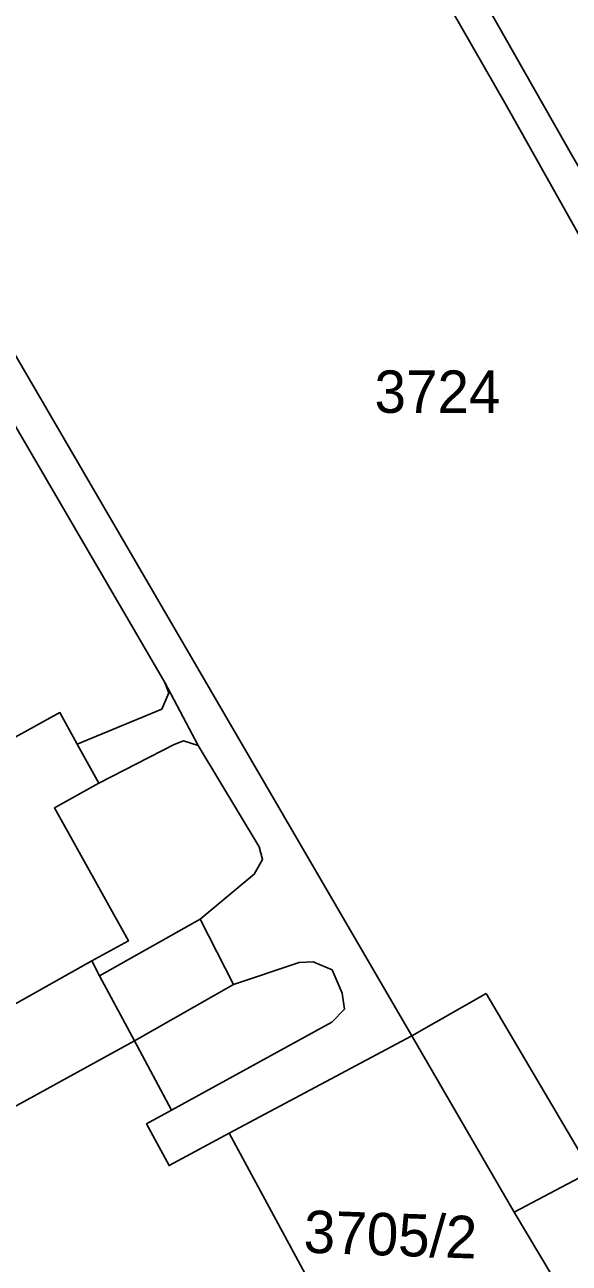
# Model space of a CAD drawing. Extents: x -262715 to -259381, y -1237238 to -1231182.
# Drawn here: x -261764.4 to -261738.7, y -1235545.6 to -1235487.1 of the extents above; entities that cross this region are included whole.
import ezdxf

# ---------------------------------------------------------------- set-up
doc = ezdxf.new("R2010")
doc.units = 0
for name, color, linetype in [('body_kn', 7, 'Continuous'), ('kladpar_druhypozemkov', 7, 'Continuous'), ('kladpar_hranice', 7, 'Continuous'), ('kladpar_parcelnecisla', 7, 'Continuous'), ('kladpar_plochy', 7, 'Continuous'), ('zappar_hrandruhpozemk', 7, 'Continuous')]:
    doc.layers.add(name, color=color, linetype=linetype)

msp = doc.modelspace()

# ---------------------------------------------------------------- linework, layer by layer
at = {"layer": 'body_kn'}
for p, q in [((-261741.69, -1235490.92), (-261741.69, -1235490.92)), ((-261757.81, -1235518.16), (-261757.81, -1235518.16)), ((-261757.81, -1235518.16), (-261757.81, -1235518.16)), ((-261757.61, -1235518.64), (-261757.61, -1235518.64)), ((-261762.76, -1235519.57), (-261762.76, -1235519.57)), ((-261757.94, -1235519.41), (-261757.94, -1235519.41)), ((-261756.92, -1235520.9), (-261756.92, -1235520.9)), ((-261761.94, -1235521.06), (-261761.94, -1235521.06)), ((-261757.36, -1235521.08), (-261757.36, -1235521.08)), ((-261756.23, -1235521.12), (-261756.23, -1235521.12)), ((-261760.92, -1235522.9), (-261760.92, -1235522.9)), ((-261760.92, -1235522.9), (-261760.92, -1235522.9)), ((-261763.02, -1235524.07), (-261763.02, -1235524.07)), ((-261753.35, -1235525.9), (-261753.35, -1235525.9)), ((-261753.19, -1235526.5), (-261753.19, -1235526.5)), ((-261753.58, -1235527.19), (-261753.58, -1235527.19)), ((-261756.13, -1235529.32), (-261756.13, -1235529.32)), ((-261759.52, -1235530.35), (-261759.52, -1235530.35)), ((-261761.25, -1235531.29), (-261761.25, -1235531.29)), ((-261761.25, -1235531.29), (-261761.25, -1235531.29)), ((-261751.46, -1235531.37), (-261751.46, -1235531.37)), ((-261750.8, -1235531.33), (-261750.8, -1235531.33)), ((-261760.88, -1235531.99), (-261760.88, -1235531.99)), ((-261749.9, -1235531.71), (-261749.9, -1235531.71)), ((-261754.56, -1235532.41), (-261754.56, -1235532.41)), ((-261754.56, -1235532.41), (-261754.56, -1235532.41)), ((-261749.43, -1235532.81), (-261749.43, -1235532.81)), ((-261742.63, -1235532.83), (-261742.63, -1235532.83)), ((-261749.32, -1235533.57), (-261749.32, -1235533.57)), ((-261749.92, -1235534.18), (-261749.92, -1235534.18)), ((-261746.14, -1235534.82), (-261746.14, -1235534.82)), ((-261746.14, -1235534.82), (-261746.14, -1235534.82)), ((-261759.24, -1235535.06), (-261759.24, -1235535.06)), ((-261759.24, -1235535.06), (-261759.24, -1235535.06)), ((-261757.48, -1235538.34), (-261757.48, -1235538.34)), ((-261757.48, -1235538.34), (-261757.48, -1235538.34)), ((-261758.67, -1235538.98), (-261758.67, -1235538.98)), ((-261754.77, -1235539.41), (-261754.77, -1235539.41)), ((-261757.6, -1235540.95), (-261757.6, -1235540.95)), ((-261741.3, -1235543.14), (-261741.3, -1235543.14))]:
    msp.add_line(p, q, dxfattribs=at)
at = {"layer": 'kladpar_druhypozemkov'}
for p, q in [((-261745.23, -1235503.27), (-261745.23, -1235503.27)), ((-261746.47, -1235543.12), (-261746.47, -1235543.12))]:
    msp.add_line(p, q, dxfattribs=at)
at = {"layer": 'kladpar_hranice'}
for points in [[(-261703.82, -1235554.81), (-261717.49, -1235533.49), (-261720.95, -1235535.54), (-261724.65, -1235529.36), (-261721.21, -1235527.35), (-261741.69, -1235490.92), (-261746.46, -1235482.59), (-261762.17, -1235454.92), (-261767.41, -1235457.85), (-261769.12, -1235454.68), (-261763.9, -1235451.67), (-261773.09, -1235436.12), (-261752.11, -1235424.22), (-261749.95, -1235426.33)], [(-261702.44, -1235554.03), (-261718.94, -1235528.05), (-261721.43, -1235523.65), (-261727.61, -1235512.61), (-261729.76, -1235508.8), (-261736.11, -1235497.5), (-261738.53, -1235493.35), (-261744.87, -1235482.21), (-261747.16, -1235478.14), (-261753.42, -1235467.18), (-261755.87, -1235462.99), (-261762.27, -1235451.12), (-261763.94, -1235448.17), (-261769.25, -1235438.72), (-261769.14, -1235437.7), (-261768.42, -1235436.65), (-261749.95, -1235426.33)], [(-261749.95, -1235426.33), (-261768.42, -1235436.65), (-261769.14, -1235437.7), (-261769.25, -1235438.72), (-261763.94, -1235448.17), (-261762.27, -1235451.12), (-261755.87, -1235462.99), (-261753.42, -1235467.18), (-261747.16, -1235478.14), (-261744.87, -1235482.21), (-261738.53, -1235493.35), (-261736.11, -1235497.5), (-261729.76, -1235508.8), (-261727.61, -1235512.61), (-261721.43, -1235523.65), (-261718.94, -1235528.05), (-261702.44, -1235554.03)], [(-261738.88, -1235547.2), (-261741.3, -1235543.14), (-261746.14, -1235534.82), (-261766.01, -1235500.78), (-261784.25, -1235467.69), (-261779.97, -1235465.46), (-261783.5, -1235458.95), (-261787.77, -1235460.98), (-261787.21, -1235451.46), (-261786.03, -1235450.8), (-261783.26, -1235442.31), (-261774.22, -1235436.76), (-261773.09, -1235436.12)], [(-261773.09, -1235436.12), (-261763.9, -1235451.67), (-261769.12, -1235454.68), (-261767.41, -1235457.85), (-261762.17, -1235454.92), (-261746.46, -1235482.59), (-261741.69, -1235490.92), (-261721.21, -1235527.35), (-261724.65, -1235529.36), (-261720.95, -1235535.54), (-261717.49, -1235533.49), (-261703.82, -1235554.81)], [(-261784.25, -1235467.69), (-261766.01, -1235500.78), (-261746.14, -1235534.82), (-261754.77, -1235539.41), (-261757.6, -1235540.95), (-261758.67, -1235538.98), (-261757.48, -1235538.34), (-261759.24, -1235535.06), (-261760.88, -1235531.99), (-261756.13, -1235529.32), (-261753.58, -1235527.19), (-261753.19, -1235526.5), (-261753.35, -1235525.9), (-261756.23, -1235521.12), (-261757.81, -1235518.16), (-261764.84, -1235506.09), (-261766.79, -1235502.5), (-261773.05, -1235491.54), (-261775.39, -1235487.37), (-261780.72, -1235477.75)], [(-261764.84, -1235506.09), (-261757.81, -1235518.16), (-261756.23, -1235521.12), (-261753.35, -1235525.9), (-261753.19, -1235526.5), (-261753.58, -1235527.19), (-261756.13, -1235529.32), (-261760.88, -1235531.99), (-261761.25, -1235531.29), (-261759.52, -1235530.35), (-261763.02, -1235524.07), (-261760.92, -1235522.9), (-261761.94, -1235521.06), (-261762.76, -1235519.57), (-261764.87, -1235520.74)], [(-261764.87, -1235520.74), (-261762.76, -1235519.57), (-261761.94, -1235521.06), (-261760.92, -1235522.9), (-261763.02, -1235524.07), (-261759.52, -1235530.35), (-261761.25, -1235531.29), (-261770.7, -1235536.59)], [(-261761.25, -1235531.29), (-261760.88, -1235531.99), (-261759.24, -1235535.06), (-261757.48, -1235538.34), (-261758.67, -1235538.98), (-261757.6, -1235540.95), (-261754.77, -1235539.41), (-261750.13, -1235547.98), (-261766.24, -1235556.71), (-261770.67, -1235548.22), (-261768.63, -1235547.14), (-261771.43, -1235541.78), (-261769.83, -1235540.88), (-261771.8, -1235537.18), (-261770.7, -1235536.59), (-261761.25, -1235531.29)], [(-261746.14, -1235534.82), (-261741.3, -1235543.14), (-261738.88, -1235547.2), (-261741.8, -1235550.13), (-261746.67, -1235553.76), (-261753.87, -1235558.39), (-261761.62, -1235567.2), (-261765.27, -1235558.85), (-261766.24, -1235556.71), (-261750.13, -1235547.98), (-261754.77, -1235539.41), (-261746.14, -1235534.82)]]:
    msp.add_lwpolyline(points, dxfattribs=at)
at = {"layer": 'kladpar_plochy'}
for points in [[(-261738.88, -1235547.2), (-261741.3, -1235543.14), (-261746.14, -1235534.82), (-261766.01, -1235500.78), (-261784.25, -1235467.69), (-261779.97, -1235465.46), (-261783.5, -1235458.95), (-261787.77, -1235460.98), (-261787.21, -1235451.46), (-261786.03, -1235450.8), (-261783.26, -1235442.31), (-261774.22, -1235436.76), (-261773.09, -1235436.12), (-261763.9, -1235451.67), (-261769.12, -1235454.68), (-261767.41, -1235457.85), (-261762.17, -1235454.92), (-261746.46, -1235482.59), (-261741.69, -1235490.92), (-261721.21, -1235527.35), (-261724.65, -1235529.36), (-261720.95, -1235535.54), (-261717.49, -1235533.49), (-261703.82, -1235554.81)], [(-261784.25, -1235467.69), (-261766.01, -1235500.78), (-261746.14, -1235534.82), (-261754.77, -1235539.41), (-261757.6, -1235540.95), (-261758.67, -1235538.98), (-261757.48, -1235538.34), (-261759.24, -1235535.06), (-261760.88, -1235531.99), (-261756.13, -1235529.32), (-261753.58, -1235527.19), (-261753.19, -1235526.5), (-261753.35, -1235525.9), (-261756.23, -1235521.12), (-261757.81, -1235518.16), (-261764.84, -1235506.09), (-261766.79, -1235502.5), (-261773.05, -1235491.54), (-261775.39, -1235487.37), (-261780.72, -1235477.75)], [(-261702.44, -1235554.03), (-261718.94, -1235528.05), (-261721.43, -1235523.65), (-261727.61, -1235512.61), (-261729.76, -1235508.8), (-261736.11, -1235497.5), (-261738.53, -1235493.35), (-261744.87, -1235482.21)], [(-261744.87, -1235482.21), (-261738.53, -1235493.35), (-261736.11, -1235497.5), (-261729.76, -1235508.8), (-261727.61, -1235512.61), (-261721.43, -1235523.65), (-261718.94, -1235528.05), (-261702.44, -1235554.03)], [(-261703.82, -1235554.81), (-261717.49, -1235533.49), (-261720.95, -1235535.54), (-261724.65, -1235529.36), (-261721.21, -1235527.35), (-261741.69, -1235490.92), (-261746.46, -1235482.59)], [(-261764.84, -1235506.09), (-261757.81, -1235518.16), (-261756.23, -1235521.12), (-261753.35, -1235525.9), (-261753.19, -1235526.5), (-261753.58, -1235527.19), (-261756.13, -1235529.32), (-261760.88, -1235531.99), (-261761.25, -1235531.29), (-261759.52, -1235530.35), (-261763.02, -1235524.07), (-261760.92, -1235522.9), (-261761.94, -1235521.06), (-261762.76, -1235519.57), (-261764.87, -1235520.74)], [(-261764.87, -1235520.74), (-261762.76, -1235519.57), (-261761.94, -1235521.06), (-261760.92, -1235522.9), (-261763.02, -1235524.07), (-261759.52, -1235530.35), (-261761.25, -1235531.29), (-261770.7, -1235536.59)]]:
    msp.add_lwpolyline(points, dxfattribs=at)
for points in [[(-261761.25, -1235531.29), (-261760.88, -1235531.99), (-261759.24, -1235535.06), (-261757.48, -1235538.34), (-261758.67, -1235538.98), (-261757.6, -1235540.95), (-261754.77, -1235539.41), (-261750.13, -1235547.98), (-261766.24, -1235556.71), (-261770.67, -1235548.22), (-261768.63, -1235547.14), (-261771.43, -1235541.78), (-261769.83, -1235540.88), (-261771.8, -1235537.18), (-261770.7, -1235536.59)], [(-261746.14, -1235534.82), (-261741.3, -1235543.14), (-261738.88, -1235547.2), (-261741.8, -1235550.13), (-261746.67, -1235553.76), (-261753.87, -1235558.39), (-261761.62, -1235567.2), (-261765.27, -1235558.85), (-261766.24, -1235556.71), (-261750.13, -1235547.98), (-261754.77, -1235539.41)]]:
    msp.add_lwpolyline(points, close=True, dxfattribs=at)
at = {"layer": 'zappar_hrandruhpozemk'}
for p, q in [((-261757.94, -1235519.41), (-261761.94, -1235521.06)), ((-261760.92, -1235522.9), (-261757.36, -1235521.08)), ((-261754.56, -1235532.41), (-261756.13, -1235529.32)), ((-261759.24, -1235535.06), (-261754.56, -1235532.41)), ((-261746.14, -1235534.82), (-261742.63, -1235532.83)), ((-261742.63, -1235532.83), (-261737.67, -1235541.23)), ((-261757.48, -1235538.34), (-261749.92, -1235534.18)), ((-261759.24, -1235535.06), (-261769.83, -1235540.88)), ((-261737.67, -1235541.23), (-261741.3, -1235543.14))]:
    msp.add_line(p, q, dxfattribs=at)
for points in [[(-261757.81, -1235518.16), (-261757.61, -1235518.64), (-261757.94, -1235519.41)], [(-261757.36, -1235521.08), (-261756.92, -1235520.9), (-261756.23, -1235521.12)], [(-261749.92, -1235534.18), (-261749.32, -1235533.57), (-261749.43, -1235532.81), (-261749.9, -1235531.71), (-261750.8, -1235531.33), (-261751.46, -1235531.37), (-261754.56, -1235532.41)]]:
    msp.add_lwpolyline(points, dxfattribs=at)

# ---------------------------------------------------------------- texts
at = {"layer": 'kladpar_parcelnecisla'}
msp.add_text('3724', height=2, dxfattribs=at).set_placement((-261747.902, -1235505.43))
msp.add_text('3705/2', height=2, rotation=358, dxfattribs=at).set_placement((-261751.27, -1235545.052))

doc.saveas('drawing.dxf')
